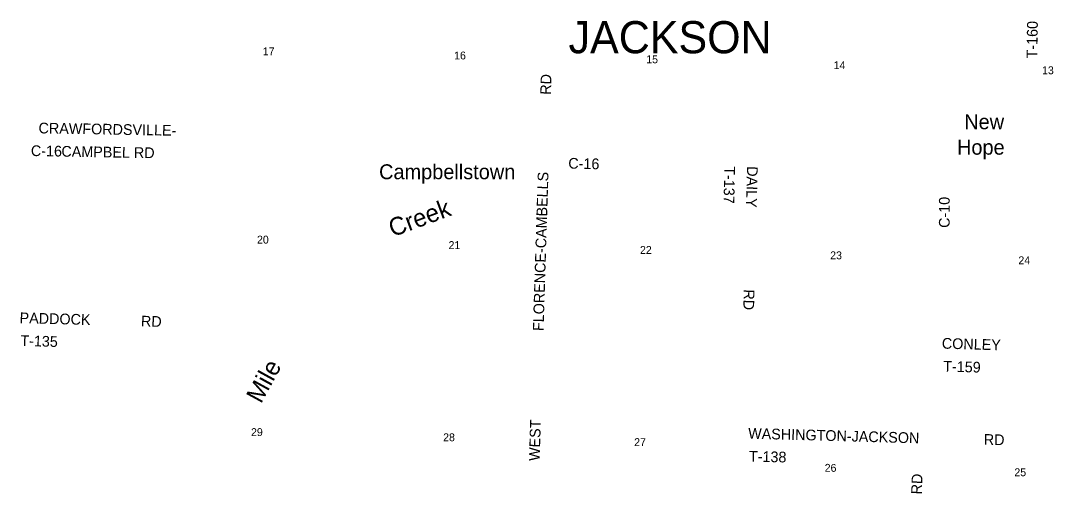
# Model space of a CAD drawing. Extents: x -21.9 to 47.3, y 14.1 to 48.7.
# Drawn here: x 2.126 to 6.255, y 14.144 to 16.035 of the extents above; entities that cross this region are included whole.
import ezdxf

# ---------------------------------------------------------------- set-up
doc = ezdxf.new("R2010")
doc.units = 0
for name, color, linetype in [('GM_X_County_Road_Text', 7, 'Continuous'), ('GM_X_Major_River_Text', 7, 'Continuous'), ('GM_X_Section_Text', 7, 'Continuous'), ('GM_X_Township_Road_Text', 7, 'Continuous'), ('GM_X_Township_Text', 7, 'Continuous'), ('GM_X_Unincorporated_Text', 7, 'Continuous')]:
    doc.layers.add(name, color=color, linetype=linetype)

msp = doc.modelspace()

# ---------------------------------------------------------------- texts
at = {"layer": 'GM_X_County_Road_Text'}
for s, height, rotation, p in [('RD', 0.04286, 88.5184, (4.2462, 15.7381)), ('CRAWFORDSVILLE-', 0.042857, 358.9809, (2.1973, 15.5842)), ('C-16', 0.04286, 358.9701, (2.1667, 15.4935)), ('CAMPBEL RD', 0.04286, 359.0273, (2.2887, 15.491)), ('C-16', 0.04286, 358.6287, (4.3153, 15.4433)), ('FLORENCE-CAMBELLS', 0.042857, 88.2239, (4.2167, 14.7928)), ('C-10', 0.04286, 90, (5.8404, 15.2059)), ('WEST', 0.04286, 88.2337, (4.201, 14.273)), ('RD', 0.04286, 88.0252, (5.729, 14.1392))]:
    msp.add_text(s, height=height, rotation=rotation, dxfattribs=at).set_placement(p)
at = {"layer": 'GM_X_Major_River_Text'}
for s, height, rotation, p in [('Creek', 0.07142, 20.2646, (3.6134, 15.1685)), ('Mile', 0.0714, 61.3024, (3.087, 14.5))]:
    msp.add_text(s, height=height, rotation=rotation, dxfattribs=at).set_placement(p)
at = {"layer": 'GM_X_Section_Text'}
for s, p in [('17', (3.0942, 15.8965)), ('16', (3.8592, 15.8798)), ('15', (4.6273, 15.8645)), ('14', (5.3766, 15.8411)), ('13', (6.2097, 15.8207)), ('20', (3.071, 15.1431)), ('21', (3.8369, 15.1213)), ('22', (4.6022, 15.1019)), ('23', (5.3627, 15.0803)), ('24', (6.1151, 15.0604)), ('29', (3.0471, 14.3731)), ('28', (3.8152, 14.3524)), ('27', (4.5789, 14.3329)), ('26', (5.3407, 14.2301)), ('25', (6.0991, 14.2125))]:
    msp.add_text(s, height=0.03157, rotation=0, dxfattribs=at).set_placement(p)
at = {"layer": 'GM_X_Township_Road_Text'}
for s, height, rotation, p in [('T-160', 0.04286, 89.1574, (6.1905, 15.8837)), ('T-137', 0.04286, 268.5959, (4.9398, 15.4529)), ('DAILY', 0.04286, 268.4519, (5.0305, 15.4531)), ('RD', 0.04286, 268.5184, (5.0173, 14.9604)), ('PADDOCK', 0.04286, 358.4363, (2.1214, 14.8249)), ('RD', 0.04286, 358.5175, (2.6066, 14.8117)), ('T-135', 0.04286, 358.3152, (2.1244, 14.7337)), ('CONLEY', 0.04286, 358.3056, (5.8086, 14.7231)), ('T-159', 0.04286, 358.3152, (5.8141, 14.6312)), ('WASHINGTON-JACKSON', 0.042857, 358.4023, (5.0342, 14.3629)), ('RD', 0.04286, 358.5194, (5.9764, 14.3384)), ('T-138', 0.04286, 358.5957, (5.0375, 14.271))]:
    msp.add_text(s, height=height, rotation=rotation, dxfattribs=at).set_placement(p)
at = {"layer": 'GM_X_Township_Text'}
msp.add_text('JACKSON', height=0.12857, rotation=0, dxfattribs=at).set_placement((4.3166, 15.9045))
at = {"layer": 'GM_X_Unincorporated_Text'}
for s, height, p in [('New', 0.05957, (5.8986, 15.6006)), ('Hope', 0.05957, (5.8697, 15.4988)), ('Campbellstown', 0.059571, (3.5591, 15.4007))]:
    msp.add_text(s, height=height, rotation=0, dxfattribs=at).set_placement(p)

doc.saveas('drawing.dxf')
